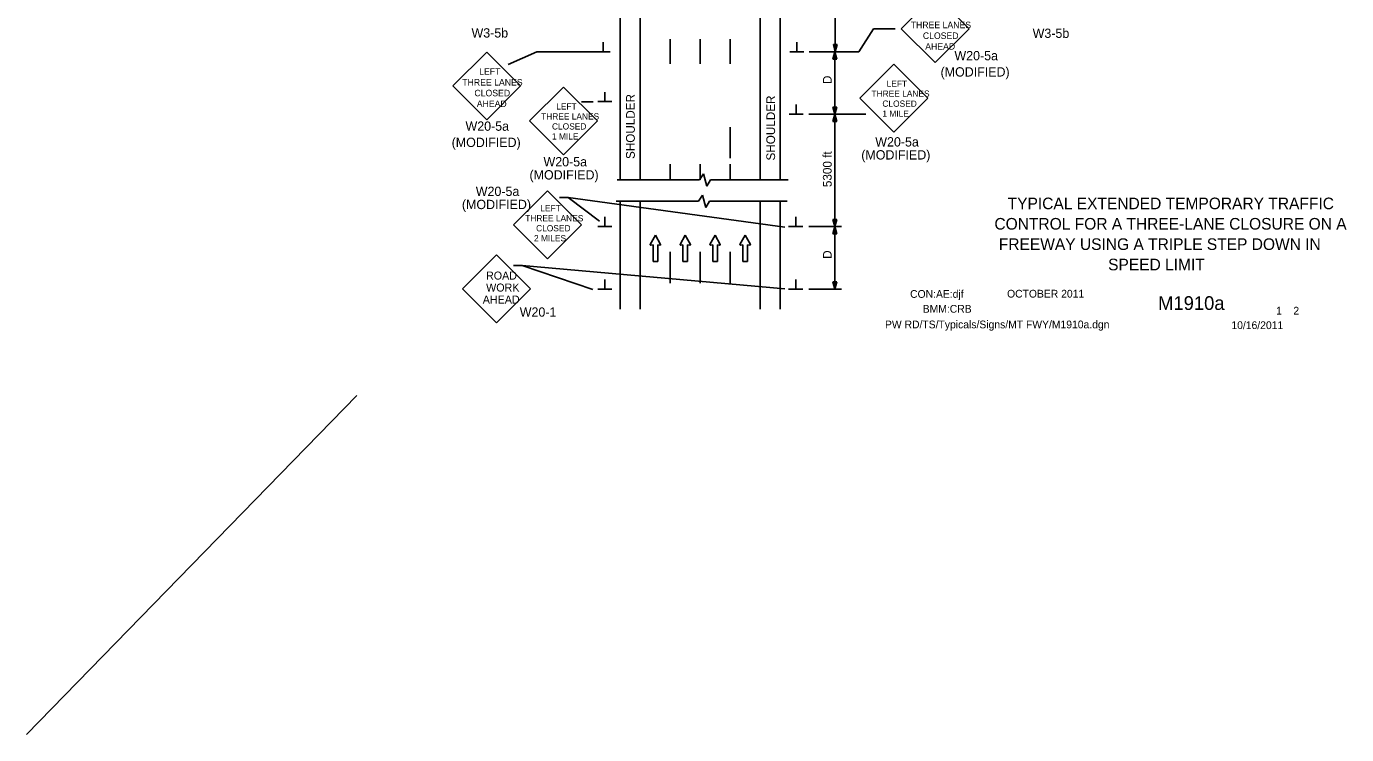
# Model space of a CAD drawing. Extents: x 16383 to 18481, y 5609 to 7023.
# Drawn here: x 16383 to 17440, y 5609 to 6175 of the extents above; entities that cross this region are included whole.
import ezdxf

# ---------------------------------------------------------------- set-up
doc = ezdxf.new("R2010")
doc.units = 0
for name, color, linetype in [('ALI_LEGAL_EX', 7, 'Continuous'), ('BORDER', 7, 'Continuous'), ('BORDER_SIGNAL_WO', 7, 'Continuous'), ('MT_SCRATCH_LEVEL_E', 7, 'Continuous'), ('PAVT_EDGE_EX', 7, 'Continuous'), ('TRAFFIC_SIGNS_PR', 7, 'Continuous'), ('TYPICAL_TEXT_DIMEN_PR', 7, 'Continuous')]:
    doc.layers.add(name, color=color, linetype=linetype)

msp = doc.modelspace()

# ---------------------------------------------------------------- linework, layer by layer
at = {"layer": 'ALI_LEGAL_EX'}
for points in [[(16898.7, 6165.2), (16898.7, 6145.3)], [(16922.7, 6165.2), (16922.7, 6145.3)], [(16946.7, 6165.2), (16946.7, 6145.3)], [(16946.7, 6069.8), (16946.7, 6094.8)], [(16898.7, 6065.2), (16898.7, 6052.6)], [(16922.7, 6065.2), (16922.7, 6052.6)], [(16946.7, 6065.2), (16946.7, 6052.6)], [(16898.7, 5994.8), (16898.7, 5969.8)], [(16922.7, 5994.8), (16922.7, 5969.8)], [(16946.7, 5994.8), (16946.7, 5969.8)]]:
    msp.add_lwpolyline(points, dxfattribs=at)
at = {"layer": 'MT_SCRATCH_LEVEL_E'}
for p, q in [((16886.8, 6008.2), (16882.7, 6000.9)), ((16890.9, 6000.9), (16886.8, 6008.2)), ((16910.7, 6008.2), (16906.6, 6000.9)), ((16914.8, 6000.9), (16910.7, 6008.2)), ((16934.6, 6008.2), (16930.5, 6000.9)), ((16938.7, 6000.9), (16934.6, 6008.2)), ((16958.7, 6008.2), (16954.5, 6000.9)), ((16962.8, 6000.9), (16958.7, 6008.2)), ((16883.2, 6000.3), (16884.9, 6000.6)), ((16884.9, 6000.6), (16884.9, 5987.3)), ((16888.7, 5987.3), (16888.7, 6000.6)), ((16888.7, 6000.6), (16890.5, 6000.3)), ((16907.1, 6000.3), (16908.8, 6000.6)), ((16908.8, 6000.6), (16908.8, 5987.3)), ((16912.6, 5987.3), (16912.6, 6000.6)), ((16912.6, 6000.6), (16914.4, 6000.3)), ((16931, 6000.3), (16932.7, 6000.6)), ((16932.7, 6000.6), (16932.7, 5987.3)), ((16936.5, 5987.3), (16936.5, 6000.6)), ((16936.5, 6000.6), (16938.3, 6000.3)), ((16955, 6000.3), (16956.8, 6000.6)), ((16956.8, 6000.6), (16956.8, 5987.3)), ((16960.5, 5987.3), (16960.5, 6000.6)), ((16960.5, 6000.6), (16962.3, 6000.3)), ((16884.9, 5987.3), (16888.7, 5987.3)), ((16908.8, 5987.3), (16912.6, 5987.3)), ((16932.7, 5987.3), (16936.5, 5987.3)), ((16956.8, 5987.3), (16960.5, 5987.3))]:
    msp.add_line(p, q, dxfattribs=at)
for centre, start, end in [((16883.1, 6000.7), 150.4248, 279.9638), ((16890.5, 6000.7), 260.0362, 29.7731), ((16907, 6000.7), 150.4248, 279.9638), ((16914.4, 6000.7), 260.0362, 29.7731), ((16930.9, 6000.7), 150.4248, 279.9638), ((16938.3, 6000.7), 260.0362, 29.7731), ((16954.9, 6000.7), 150.4248, 279.9638), ((16962.4, 6000.7), 260.0362, 29.7731)]:
    msp.add_arc(centre, 0.463, start, end, dxfattribs=at)
at = {"layer": 'PAVT_EDGE_EX'}
for p, q in [((16858.7, 6927.6), (16858.7, 6052.6)), ((16874.7, 6927.6), (16874.7, 6052.6)), ((16970.7, 6927.6), (16970.7, 6052.6)), ((16986.7, 6927.6), (16986.7, 6052.6)), ((16858.7, 6035.5), (16858.7, 5949)), ((16874.7, 6035.5), (16874.7, 5949)), ((16970.7, 6035.5), (16970.7, 5949)), ((16986.7, 6035.5), (16986.7, 5949))]:
    msp.add_line(p, q, dxfattribs=at)
at = {"layer": 'TRAFFIC_SIGNS_PR'}
for p, q in [((17110.8, 6200.7), (17083.6, 6173.5)), ((17137.9, 6173.5), (17110.8, 6200.7)), ((17083.6, 6173.5), (17110.8, 6146.4)), ((17110.8, 6146.4), (17137.9, 6173.5)), ((16751.8, 6154.8), (16724.6, 6127.7)), ((16778.9, 6127.7), (16751.8, 6154.8)), ((17077.7, 6145), (17050.5, 6117.9)), ((17104.9, 6117.9), (17077.7, 6145)), ((16724.6, 6127.7), (16751.8, 6100.5)), ((16751.8, 6100.5), (16778.9, 6127.7)), ((16813.2, 6126.8), (16786, 6099.7)), ((16840.4, 6099.7), (16813.2, 6126.8)), ((17050.5, 6117.9), (17077.7, 6090.7)), ((17077.7, 6090.7), (17104.9, 6117.9)), ((16786, 6099.7), (16813.2, 6072.5)), ((16813.2, 6072.5), (16840.4, 6099.7)), ((16800.5, 6043.7), (16773.3, 6016.5)), ((16827.7, 6016.5), (16800.5, 6043.7)), ((16773.3, 6016.5), (16800.5, 5989.3)), ((16800.5, 5989.3), (16827.7, 6016.5)), ((16759.7, 5992.4), (16732.5, 5965.2)), ((16786.8, 5965.2), (16759.7, 5992.4)), ((16732.5, 5965.2), (16759.7, 5938)), ((16759.7, 5938), (16786.8, 5965.2)), ((16647.8, 5880), (16383.3, 5608.6))]:
    msp.add_line(p, q, dxfattribs=at)
at = {"layer": 'TYPICAL_TEXT_DIMEN_PR'}
for p, q in [((17030.8, 6205), (17030.8, 6155)), ((17049.7, 6155), (17061.3, 6173.4)), ((17078.8, 6173.4), (17061.3, 6173.4)), ((16844.9, 6155), (16844.9, 6162.8)), ((17000, 6155), (17000, 6162.8)), ((16791.8, 6154.9), (16768.9, 6144.8)), ((16844.9, 6155), (16791.8, 6154.9)), ((16850.6, 6155), (16839.3, 6155)), ((17005.6, 6155), (16994.3, 6155)), ((17049.7, 6155), (17009.8, 6155)), ((17028.9, 6149.1), (17030.5, 6155)), ((17030.8, 6155), (17029.3, 6160.8)), ((17029.3, 6160.8), (17030.8, 6160.8)), ((17030.5, 6155), (17030.5, 6105)), ((17030.5, 6155), (17032, 6149.1)), ((17030.8, 6160.8), (17032.4, 6160.8)), ((17032.4, 6160.8), (17030.8, 6155)), ((17030.5, 6149.1), (17028.9, 6149.1)), ((17032, 6149.1), (17030.5, 6149.1)), ((16846.3, 6115.1), (16846.3, 6122.8)), ((16837, 6115), (16827.7, 6115)), ((16840.7, 6115.1), (16851.9, 6115.1)), ((16999.6, 6105), (16999.6, 6112.8)), ((17030.5, 6105), (17028.9, 6110.8)), ((17028.9, 6110.8), (17030.5, 6110.8)), ((17030.5, 6110.8), (17032, 6110.8)), ((17032, 6110.8), (17030.5, 6105)), ((17005.2, 6105), (16994, 6105)), ((17055.2, 6105), (17009.5, 6105)), ((17028.9, 6099.1), (17030.5, 6105)), ((17030.5, 6099.1), (17028.9, 6099.1)), ((17030.5, 6105), (17030.5, 6015.1)), ((17030.5, 6105), (17032.1, 6099.1)), ((17032.1, 6099.1), (17030.5, 6099.1)), ((16925.3, 6057.4), (16922, 6052.6)), ((16928, 6047.5), (16925.3, 6057.4)), ((16922, 6052.6), (16856.1, 6052.6)), ((16930.8, 6052.6), (16928, 6047.5)), ((16993.1, 6052.6), (16930.8, 6052.6)), ((16816.9, 6038.5), (16809.9, 6038.5)), ((16842.1, 6019.5), (16816.9, 6038.5)), ((16816.9, 6038.5), (16990.5, 6014.6)), ((16921.3, 6035.5), (16855.3, 6035.5)), ((16924.5, 6040.3), (16921.3, 6035.5)), ((16927.2, 6030.3), (16924.5, 6040.3)), ((16930, 6035.5), (16927.2, 6030.3)), ((16992.3, 6035.5), (16930, 6035.5)), ((16840.7, 6015.1), (16851.9, 6015.1)), ((16846.3, 6015.1), (16846.3, 6022.8)), ((17004.7, 6015.1), (16993.4, 6015.1)), ((16999.1, 6015.1), (16999.1, 6022.8)), ((17035.7, 6015.1), (17009.7, 6015.1)), ((17030.5, 6015.1), (17028.9, 6020.9)), ((17028.9, 6020.9), (17030.5, 6020.9)), ((17028.9, 6009.2), (17030.5, 6015.1)), ((17030.5, 6020.9), (17032.1, 6020.9)), ((17032.1, 6020.9), (17030.5, 6015.1)), ((17030.5, 6015.1), (17030.5, 5965.1)), ((17030.5, 6015.1), (17032.1, 6009.2)), ((17030.5, 6009.2), (17028.9, 6009.2)), ((17032.1, 6009.2), (17030.5, 6009.2)), ((16780.1, 5984.1), (16773.1, 5984.1)), ((16780.1, 5984.1), (16836.8, 5964.8)), ((16780.1, 5984.1), (16990.5, 5965.2)), ((16846.3, 5965.1), (16846.3, 5972.8)), ((16999.1, 5965.1), (16999.1, 5972.8)), ((16840.7, 5965.1), (16851.9, 5965.1)), ((17004.7, 5965.1), (16993.4, 5965.1)), ((17035.7, 5965.1), (17009.7, 5965.1)), ((17030.5, 5965.1), (17028.9, 5970.9)), ((17028.9, 5970.9), (17030.5, 5970.9)), ((17030.5, 5970.9), (17032.1, 5970.9)), ((17032.1, 5970.9), (17030.5, 5965.1))]:
    msp.add_line(p, q, dxfattribs=at)

# ---------------------------------------------------------------- texts
at = {"layer": 'BORDER'}
for s, p in [('TYPICAL EXTENDED TEMPORARY TRAFFIC', (17168.8, 6029)), ('CONTROL FOR A THREE-LANE CLOSURE ON A', (17158.2, 6012.7)), ('FREEWAY USING A TRIPLE STEP DOWN IN ', (17161.7, 5996.4)), ('SPEED LIMIT', (17249.2, 5980.1))]:
    msp.add_text(s, height=9.3, dxfattribs=at).set_placement(p)
at = {"layer": 'BORDER_SIGNAL_WO'}
for s, height, p in [('CON:AE:djf  ', 6.2, (17090.7, 5958.1)), ('    OCTOBER 2011', 6.2, (17159.1, 5958.3)), ('BMM:CRB', 6.2, (17100.8, 5946.2)), ('    M1910a   ', 11, (17272.9, 5948.4)), (' 1    2 ', 6.2, (17381.4, 5944.7)), ('PW RD/TS/Typicals/Signs/MT FWY/M1910a.dgn      ', 6.2, (17070.6, 5933.7)), ('10/16/2011', 6.2, (17347.9, 5933.1))]:
    msp.add_text(s, height=height, dxfattribs=at).set_placement(p)
at = {"layer": 'TRAFFIC_SIGNS_PR'}
for s, height, p in [('W3-5b', 7.44, (16739.6, 6166.4)), ('THREE LANES', 5.2, (17091.2, 6173.9)), ('W3-5b', 7.44, (17188.8, 6166.1)), ('CLOSED', 5.2, (17100.9, 6165.3)), ('AHEAD', 5.2, (17102.8, 6156.7)), ('W20-5a', 7.44, (17126.2, 6148.2)), ('LEFT', 5.2, (16745.7, 6136.6)), ('(MODIFIED)', 7.44, (17115.1, 6135.2)), ('THREE LANES', 5.2, (16732.2, 6128)), ('LEFT', 5.01, (17071.9, 6127)), ('CLOSED', 5.2, (16741.9, 6119.4)), ('THREE LANES', 5.006, (17059.8, 6119)), ('AHEAD', 5.2, (16743.8, 6110.8)), ('LEFT', 5.01, (16807.4, 6108.8)), ('CLOSED', 5.01, (17068.5, 6111)), ('W20-5a', 7.44, (16734.8, 6091.8)), ('THREE LANES', 5.006, (16795.3, 6100.8)), ('1 MILE', 5.01, (17068.5, 6103)), ('CLOSED', 5.01, (16804, 6092.8)), ('1 MILE', 5.01, (16804, 6084.8)), ('(MODIFIED)', 7.44, (16723.7, 6078.8)), ('W20-5a', 7.45, (17062.8, 6079.2)), ('W20-5a', 7.45, (16797.2, 6063.3)), ('(MODIFIED)', 7.45, (17051.6, 6068.8)), ('(MODIFIED)', 7.45, (16786, 6052.8)), ('W20-5a', 7.45, (16743, 6039.6)), ('(MODIFIED)', 7.45, (16731.9, 6029.1)), ('THREE LANES', 5.006, (16782.6, 6019.3)), ('LEFT', 5.01, (16794.7, 6027.3)), ('CLOSED', 5.01, (16791.3, 6011.3)), ('2 MILES', 5.01, (16789.6, 6003.3)), ('ROAD', 6.41, (16751.2, 5972.7)), ('WORK', 6.41, (16751.3, 5963.1)), ('AHEAD', 6.41, (16748.6, 5953.5)), ('W20-1', 7.45, (16778.2, 5943))]:
    msp.add_text(s, height=height, dxfattribs=at).set_placement(p)
at = {"layer": 'TYPICAL_TEXT_DIMEN_PR'}
for s, p in [('D', (17027.9, 6129.2)), ('SHOULDER', (16870.3, 6069.2)), ('SHOULDER', (16982.6, 6068)), ('5300 ft', (17027.9, 6046.7)), ('D', (17027.9, 5989.3))]:
    msp.add_text(s, height=7, rotation=90, dxfattribs=at).set_placement(p)

doc.saveas('drawing.dxf')
